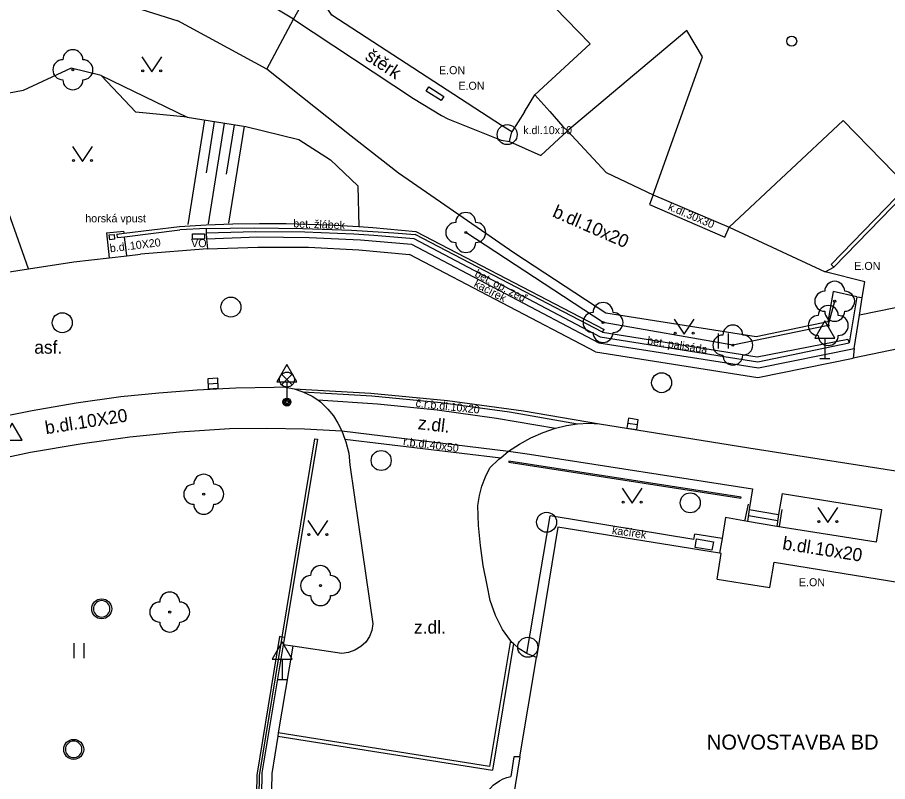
# Model space of a CAD drawing. Extents: x -598233 to -596890, y -1157848 to -1156431.
# Drawn here: x -598000.23 to -597956.73, y -1156818.81 to -1156780.59 of the extents above; entities that cross this region are included whole.
import ezdxf

# ---------------------------------------------------------------- set-up
doc = ezdxf.new("R2010")
doc.units = 0
for name, color, linetype in [('Level 10', 7, 'Continuous'), ('Level 11', 7, 'Continuous'), ('Level 14', 7, 'Continuous'), ('Level 15', 7, 'Continuous'), ('Level 22', 7, 'Continuous'), ('Level 23', 7, 'Continuous'), ('Level 24', 7, 'Continuous'), ('Level 27', 7, 'Continuous'), ('Level 28', 7, 'Continuous'), ('Level 33', 7, 'Continuous'), ('Level 34', 7, 'Continuous'), ('Level 36', 7, 'Continuous'), ('Level 40', 7, 'Continuous'), ('Level 41', 7, 'Continuous'), ('Level 42', 7, 'Continuous'), ('Level 5', 7, 'Continuous'), ('Level 6', 7, 'Continuous'), ('Level 7', 7, 'Continuous'), ('Level 8', 7, 'Continuous'), ('Level 9', 7, 'Continuous')]:
    doc.layers.add(name, color=color, linetype=linetype)

msp = doc.modelspace()

# ---------------------------------------------------------------- linework, layer by layer
at = {"layer": 'Level 10'}
for points in [[(-597990.73, -1156792.17), (-597988.21, -1156792.08), (-597985.68, -1156792.09), (-597983.16, -1156792.22), (-597980.64, -1156792.45)], [(-598000.74, -1156793.34), (-597999.67, -1156793.17), (-597997.42, -1156792.82), (-597995.65, -1156792.61), (-597994.77, -1156792.51), (-597994.08, -1156792.43)], [(-597990.73, -1156792.17), (-597994.08, -1156792.43)], [(-597971.34, -1156797.31), (-597980.64, -1156792.45)], [(-597953.48, -1156796.6), (-597958.46, -1156797.64)], [(-597971.34, -1156797.31), (-597963.22, -1156798.6)], [(-597963.22, -1156798.6), (-597958.46, -1156797.64)], [(-597995.07, -1156799.55), (-597993.16, -1156799.36), (-597991.24, -1156799.21), (-597989.32, -1156799.12), (-597987.4, -1156799.08)], [(-597987.4, -1156799.08), (-597986.91, -1156799.07), (-597986.4, -1156799.16), (-597985.97, -1156799.31)], [(-597985.97, -1156799.31), (-597985.5, -1156799.53), (-597985.22, -1156799.71), (-597985.08, -1156799.82), (-597984.71, -1156800.18)], [(-598003.87, -1156801.19), (-598001.69, -1156800.69), (-597999.49, -1156800.25), (-597997.29, -1156799.87), (-597995.07, -1156799.55)], [(-597984.71, -1156800.18), (-597984.44, -1156800.52), (-597984.21, -1156800.88), (-597984.02, -1156801.27)], [(-597975.14, -1156801.93), (-597974.56, -1156801.61), (-597973.96, -1156801.35), (-597973.33, -1156801.14)], [(-597973.33, -1156801.14), (-597972.79, -1156801), (-597972.23, -1156800.91), (-597971.69, -1156800.89), (-597971.14, -1156800.92)], [(-597971.14, -1156800.92), (-597963.67, -1156802.11)], [(-597984.02, -1156801.27), (-597983.86, -1156801.69), (-597983.81, -1156801.82)], [(-597983.81, -1156801.82), (-597983.67, -1156802.39), (-597983.61, -1156802.97)], [(-597976.61, -1156803.12), (-597976.16, -1156802.68), (-597976.07, -1156802.61), (-597975.68, -1156802.29), (-597975.14, -1156801.93)], [(-597963.67, -1156802.11), (-597953.34, -1156803.73)], [(-597983.61, -1156802.97), (-597983.19, -1156805.97)], [(-597977.21, -1156805), (-597977.14, -1156804.51), (-597977.02, -1156804.03), (-597976.84, -1156803.56), (-597976.61, -1156803.12)], [(-597977.09, -1156807), (-597977.18, -1156806), (-597977.21, -1156805)], [(-597983.19, -1156805.97), (-597982.46, -1156810.92)], [(-597976.75, -1156808.98), (-597976.95, -1156808), (-597977.09, -1156807)], [(-597976.6, -1156809.76), (-597976.75, -1156808.98)], [(-597976.34, -1156810.51), (-597976.6, -1156809.76)], [(-597975.51, -1156811.85), (-597975.58, -1156811.76), (-597975.98, -1156811.21), (-597976.34, -1156810.51)], [(-597982.46, -1156810.92), (-597982.51, -1156811.25), (-597982.63, -1156811.56), (-597982.82, -1156811.83), (-597983.07, -1156812.05)], [(-597984.02, -1156812.41), (-597986.47, -1156812.04), (-597986.94, -1156811.97)], [(-597983.07, -1156812.05), (-597983.36, -1156812.23), (-597983.68, -1156812.35), (-597984.02, -1156812.41)], [(-597974.29, -1156812.6), (-597974.74, -1156812.42), (-597974.77, -1156812.4), (-597975.15, -1156812.17), (-597975.44, -1156811.91), (-597975.51, -1156811.85)]]:
    msp.add_lwpolyline(points, dxfattribs=at)
at = {"layer": 'Level 11'}
for points in [[(-597974.37, -1156784.47), (-597971.6, -1156781.91), (-597978.08, -1156775.23), (-597959.82, -1156756.9), (-597957.84, -1156758.76), (-597959.27, -1156760.49)], [(-597986.43, -1156780.68), (-597993.45, -1156776.46)], [(-598002.82, -1156778.8), (-598002.27, -1156778.4), (-597998.93, -1156778.62), (-597992.22, -1156780.77)], [(-597986.43, -1156780.68), (-597985.5, -1156779.01)], [(-597987.77, -1156783.18), (-597992.22, -1156780.77)], [(-597987.77, -1156783.18), (-597986.43, -1156780.68)], [(-597986.43, -1156780.68), (-597980.44, -1156784.64)], [(-597968.45, -1156789.46), (-597965.98, -1156782.57), (-597966.77, -1156781.24), (-597972.73, -1156786.26)], [(-597983.55, -1156786.53), (-597987.77, -1156783.18)], [(-597980.44, -1156784.64), (-597979.03, -1156785.5)], [(-597979.03, -1156785.5), (-597978.72, -1156785.67)], [(-597978.72, -1156785.67), (-597976.05, -1156786.73)], [(-597955.75, -1156789.03), (-597958.96, -1156785.74), (-597964.65, -1156791.08)], [(-597975.63, -1156786.79), (-597975.51, -1156786.32)], [(-597974.06, -1156787.49), (-597972.73, -1156786.26)], [(-597981.18, -1156788.38), (-597983.55, -1156786.53)], [(-597976.05, -1156786.73), (-597975.63, -1156786.79)], [(-597975.63, -1156786.79), (-597974.06, -1156787.49)], [(-597975.42, -1156792.37), (-597981.18, -1156788.38)], [(-597968.45, -1156789.46), (-597968.64, -1156789.95)], [(-597968.64, -1156789.95), (-597964.87, -1156791.58)], [(-597995.27, -1156791.43), (-597994.9, -1156791.38), (-597992.13, -1156791.04)], [(-597992.13, -1156791.04), (-597990.8, -1156790.96)], [(-597990.8, -1156791.15), (-597992.11, -1156791.22)], [(-597990.8, -1156790.96), (-597989.46, -1156790.91), (-597988.13, -1156790.89), (-597986.79, -1156790.9)], [(-597986.79, -1156790.9), (-597984.63, -1156790.96), (-597983.17, -1156791.05), (-597982.47, -1156791.09), (-597980.32, -1156791.29)], [(-597964.87, -1156791.58), (-597964.65, -1156791.08)], [(-597995.78, -1156791.37), (-597994.91, -1156791.28)], [(-597995.78, -1156791.37), (-597995.65, -1156792.61)], [(-597995.27, -1156791.43), (-597995.25, -1156791.6)], [(-597995.25, -1156791.6), (-597994.88, -1156791.56), (-597992.11, -1156791.22)], [(-597994.9, -1156791.38), (-597994.91, -1156791.28)], [(-597994.77, -1156792.51), (-597994.88, -1156791.56)], [(-597990.8, -1156791.36), (-597988.33, -1156791.3), (-597985.87, -1156791.32), (-597983.41, -1156791.42)], [(-597990.78, -1156791.66), (-597988.22, -1156791.57), (-597985.65, -1156791.59), (-597983.09, -1156791.71), (-597980.53, -1156791.94)], [(-597983.41, -1156791.42), (-597982.41, -1156791.48), (-597981.42, -1156791.56), (-597980.42, -1156791.65)], [(-597980.42, -1156791.65), (-597971.1, -1156796.57)], [(-597980.32, -1156791.29), (-597970.91, -1156796.2)], [(-597990.78, -1156791.66), (-597990.73, -1156792.17)], [(-597980.53, -1156791.94), (-597971.17, -1156796.86)], [(-597970.82, -1156795.38), (-597975.42, -1156792.37)], [(-597957.87, -1156793.81), (-597959.85, -1156793.31)], [(-597958, -1156794.6), (-597957.87, -1156793.81)], [(-597959.45, -1156794.3), (-597959.73, -1156795.81)], [(-597958.27, -1156794.56), (-597959.45, -1156794.3)], [(-597958.41, -1156797.15), (-597958.14, -1156795.49), (-597958, -1156794.6)], [(-597953.56, -1156794.55), (-597958.14, -1156795.49)], [(-597963.31, -1156796.56), (-597970.82, -1156795.38)], [(-597959.73, -1156795.81), (-597963.31, -1156796.56)], [(-597970.98, -1156796.34), (-597970.91, -1156796.2)], [(-597971.17, -1156796.86), (-597963.18, -1156798.12)], [(-597971.1, -1156796.57), (-597963.22, -1156797.82)], [(-597963.22, -1156797.82), (-597958.65, -1156796.87)], [(-597963.18, -1156798.12), (-597958.41, -1156797.15)], [(-597958.41, -1156797.15), (-597958.46, -1156797.64)], [(-597986.4, -1156799.16), (-597982.56, -1156799.38), (-597978.74, -1156799.75), (-597974.93, -1156800.27), (-597971.14, -1156800.92)], [(-597985.97, -1156799.31), (-597982.51, -1156799.51), (-597979.07, -1156799.85), (-597975.64, -1156800.31), (-597972.23, -1156800.91)], [(-597985.22, -1156799.71), (-597982.23, -1156799.92), (-597979.25, -1156800.22), (-597976.28, -1156800.63), (-597973.33, -1156801.14)], [(-597999.57, -1156802.33), (-597997.1, -1156801.91), (-597994.62, -1156801.57), (-597992.13, -1156801.32), (-597989.63, -1156801.15)], [(-597989.63, -1156801.15), (-597987.76, -1156801.13), (-597985.89, -1156801.17), (-597984.02, -1156801.27)], [(-597984.02, -1156801.27), (-597975.68, -1156802.29)], [(-597985.39, -1156801.66), (-597985.24, -1156801.68), (-597986.88, -1156811.61)], [(-597983.86, -1156801.69), (-597976.07, -1156802.61)], [(-598002.86, -1156803.07), (-598001.22, -1156802.69), (-597999.57, -1156802.33)], [(-597975.68, -1156802.29), (-597974.64, -1156802.43)], [(-597974.64, -1156802.43), (-597963.48, -1156804.17)], [(-597975.66, -1156802.78), (-597975.66, -1156802.83), (-597964.07, -1156804.63), (-597964.06, -1156804.58)], [(-597963.48, -1156804.17), (-597963.65, -1156805.21)], [(-597962.01, -1156804.41), (-597962.18, -1156805.46)], [(-597962.01, -1156804.41), (-597957.04, -1156805.2)], [(-597974.77, -1156812.4), (-597973.61, -1156805.52)], [(-597966.42, -1156806.7), (-597973.61, -1156805.52)], [(-597963.65, -1156805.21), (-597963.74, -1156805.8)], [(-597963.69, -1156805.5), (-597962.22, -1156805.76)], [(-597963.65, -1156805.21), (-597962.18, -1156805.46)], [(-597962.18, -1156805.46), (-597962.27, -1156806.05)], [(-597957.04, -1156805.2), (-597957.31, -1156806.83)], [(-597964.84, -1156805.6), (-597965.01, -1156806.66), (-597965.13, -1156807.39)], [(-597963.74, -1156805.8), (-597964.84, -1156805.6)], [(-597962.27, -1156806.05), (-597963.74, -1156805.8)], [(-597966.42, -1156806.7), (-597966.37, -1156806.43)], [(-597965.01, -1156806.66), (-597966.37, -1156806.43)], [(-597957.31, -1156806.83), (-597962.27, -1156806.05)], [(-597995.6077, -1156810.17), (-597995.614, -1156810.0984), (-597995.6326, -1156810.029), (-597995.6629, -1156809.9638), (-597995.7042, -1156809.905), (-597995.755, -1156809.8542), (-597995.8138, -1156809.8129), (-597995.879, -1156809.7826), (-597995.9484, -1156809.764), (-597996.02, -1156809.7577), (-597996.0916, -1156809.764), (-597996.161, -1156809.7826), (-597996.2261, -1156809.8129), (-597996.285, -1156809.8542), (-597996.3358, -1156809.905), (-597996.3771, -1156809.9638), (-597996.4074, -1156810.029), (-597996.426, -1156810.0984), (-597996.4323, -1156810.17), (-597996.426, -1156810.2416), (-597996.4074, -1156810.311), (-597996.3771, -1156810.3761), (-597996.3358, -1156810.435), (-597996.285, -1156810.4858), (-597996.2261, -1156810.5271), (-597996.161, -1156810.5574), (-597996.0916, -1156810.576), (-597996.02, -1156810.5823), (-597995.9484, -1156810.576), (-597995.879, -1156810.5574), (-597995.8138, -1156810.5271), (-597995.755, -1156810.4858), (-597995.7042, -1156810.435), (-597995.6629, -1156810.3761), (-597995.6326, -1156810.311), (-597995.614, -1156810.2416), (-597995.6077, -1156810.17)], [(-597987.13, -1156811.56), (-597988.27, -1156818.49)], [(-597986.47, -1156812.04), (-597987.19, -1156816.38), (-597987.22, -1156816.54), (-597987.52, -1156818.41)], [(-597997.0077, -1156817.2), (-597997.014, -1156817.1284), (-597997.0326, -1156817.059), (-597997.0629, -1156816.9938), (-597997.1042, -1156816.935), (-597997.155, -1156816.8842), (-597997.2138, -1156816.8429), (-597997.279, -1156816.8126), (-597997.3484, -1156816.794), (-597997.42, -1156816.7877), (-597997.4916, -1156816.794), (-597997.561, -1156816.8126), (-597997.6261, -1156816.8429), (-597997.685, -1156816.8842), (-597997.7358, -1156816.935), (-597997.7771, -1156816.9938), (-597997.8074, -1156817.059), (-597997.826, -1156817.1284), (-597997.8323, -1156817.2), (-597997.826, -1156817.2716), (-597997.8074, -1156817.341), (-597997.7771, -1156817.4061), (-597997.7358, -1156817.465), (-597997.685, -1156817.5158), (-597997.6261, -1156817.5571), (-597997.561, -1156817.5874), (-597997.4916, -1156817.606), (-597997.42, -1156817.6123), (-597997.3484, -1156817.606), (-597997.279, -1156817.5874), (-597997.2138, -1156817.5571), (-597997.155, -1156817.5158), (-597997.1042, -1156817.465), (-597997.0629, -1156817.4061), (-597997.0326, -1156817.341), (-597997.014, -1156817.2716), (-597997.0077, -1156817.2)], [(-597975.41, -1156817.58), (-597975.56, -1156818.56)], [(-597975.11, -1156817.57), (-597975.41, -1156817.58)], [(-597988.27, -1156818.49), (-597988.44, -1156828.65), (-597988.52, -1156833.83)], [(-597987.52, -1156818.41), (-597987.79, -1156832.35)], [(-597976.13, -1156818.77), (-597975.95, -1156818.68), (-597975.76, -1156818.61), (-597975.56, -1156818.56)], [(-597976.95, -1156820.03), (-597976.88, -1156819.64), (-597976.71, -1156819.29), (-597976.45, -1156818.99), (-597976.13, -1156818.77)]]:
    msp.add_lwpolyline(points, dxfattribs=at)
at = {"layer": 'Level 14'}
msp.add_lwpolyline([(-597991.74, -1156785.58), (-597994.32, -1156785.33), (-597996.05, -1156783.5)], dxfattribs=at)
at = {"layer": 'Level 15'}
for points in [[(-597990.88, -1156785.72), (-597991.72, -1156790.94)], [(-597990.39, -1156785.8), (-597990.8, -1156788.36)], [(-597989.89, -1156785.88), (-597990.7, -1156790.91)], [(-597989.4, -1156785.96), (-597989.79, -1156788.43)], [(-597988.9, -1156786.03), (-597989.68, -1156790.88)]]:
    msp.add_lwpolyline(points, dxfattribs=at)
at = {"layer": 'Level 22'}
for centre in [(-597997.46, -1156783.21), (-597977.82, -1156791.35), (-597959.38, -1156794.79), (-597970.96, -1156795.85), (-597959.7, -1156796), (-597964.47, -1156796.98), (-597990.92, -1156804.44), (-597985.08, -1156809.01), (-597992.62, -1156810.33)]:
    msp.add_circle(centre, 0.05, dxfattribs=at)
for centre, start, end in [((-597997.46, -1156782.71), 0, 180), ((-597997.96, -1156783.21), 90, 270), ((-597996.96, -1156783.21), 270, 90), ((-597997.46, -1156783.71), 180, 0), ((-597977.82, -1156790.85), 0, 180), ((-597978.32, -1156791.35), 90, 270), ((-597977.32, -1156791.35), 270, 90), ((-597977.82, -1156791.85), 180, 0), ((-597959.38, -1156794.29), 0, 180), ((-597959.88, -1156794.79), 90, 270), ((-597958.88, -1156794.79), 270, 90), ((-597970.96, -1156795.35), 0, 180), ((-597959.7, -1156795.5), 0, 180), ((-597971.46, -1156795.85), 90, 270), ((-597970.46, -1156795.85), 270, 90), ((-597960.2, -1156796), 90, 270), ((-597959.38, -1156795.29), 180, 0), ((-597959.2, -1156796), 270, 90), ((-597964.47, -1156796.48), 0, 180), ((-597970.96, -1156796.35), 180, 0), ((-597964.97, -1156796.98), 90, 270), ((-597963.97, -1156796.98), 270, 90), ((-597959.7, -1156796.5), 180, 0), ((-597964.47, -1156797.48), 180, 0), ((-597990.92, -1156803.94), 0, 180), ((-597991.42, -1156804.44), 90, 270), ((-597990.42, -1156804.44), 270, 90), ((-597990.92, -1156804.94), 180, 0), ((-597985.08, -1156808.51), 0, 180), ((-597985.58, -1156809.01), 90, 270), ((-597984.58, -1156809.01), 270, 90), ((-597992.62, -1156809.83), 0, 180), ((-597993.12, -1156810.33), 90, 270), ((-597992.12, -1156810.33), 270, 90), ((-597985.08, -1156809.51), 180, 0), ((-597992.62, -1156810.83), 180, 0)]:
    msp.add_arc(centre, 0.5, start, end, dxfattribs=at)
at = {"layer": 'Level 23'}
for points in [[(-597996.05, -1156783.5), (-597997.54, -1156783.13), (-597999.95, -1156784.24), (-598002.66, -1156784.77)], [(-597996.05, -1156783.5), (-597991.74, -1156785.58)], [(-597999.67, -1156793.17), (-598002.66, -1156784.77)], [(-597991.74, -1156785.58), (-597988.81, -1156786.05), (-597986.17, -1156786.7), (-597984.58, -1156787.71)], [(-597984.58, -1156787.71), (-597983.21, -1156789.02), (-597983.17, -1156791.05)]]:
    msp.add_lwpolyline(points, dxfattribs=at)
at = {"layer": 'Level 24'}
for points in [[(-597979.8, -1156784.28), (-597979.67, -1156784.07), (-597978.92, -1156784.54), (-597979.05, -1156784.75)], [(-597979.05, -1156784.75), (-597979.8, -1156784.28)], [(-597995.64, -1156791.47), (-597995.4, -1156791.44)], [(-597995.62, -1156791.71), (-597995.64, -1156791.47)], [(-597995.4, -1156791.44), (-597995.38, -1156791.69)], [(-597991.48, -1156791.66), (-597991.48, -1156791.41)], [(-597991.48, -1156791.41), (-597990.88, -1156791.42)], [(-597990.88, -1156791.42), (-597990.88, -1156791.67)], [(-597995.38, -1156791.69), (-597995.62, -1156791.71)], [(-597991.48, -1156791.66), (-597990.88, -1156791.67)], [(-597965.52, -1156807.24), (-597966.36, -1156807.11), (-597966.28, -1156806.67), (-597965.44, -1156806.82)], [(-597965.44, -1156806.82), (-597965.52, -1156807.24)], [(-597975.58, -1156811.76), (-597976.63, -1156818.06)], [(-597975.44, -1156811.91), (-597976.49, -1156818.24)], [(-597976.63, -1156818.06), (-597987.19, -1156816.38)], [(-597987.22, -1156816.54), (-597976.49, -1156818.24)]]:
    msp.add_lwpolyline(points, dxfattribs=at)
at = {"layer": 'Level 27'}
for p, q in [((-597990.6998, -1156798.9106), (-597990.2002, -1156798.8894)), ((-597969.7272, -1156800.8827), (-597969.2328, -1156800.9573))]:
    msp.add_line(p, q, dxfattribs=at)
for points in [[(-597990.6892, -1156799.1604), (-597990.1896, -1156799.1392), (-597990.2108, -1156798.6396), (-597990.7104, -1156798.6608)], [(-597969.7645, -1156801.1299), (-597969.2701, -1156801.2045), (-597969.1955, -1156800.7101), (-597969.6899, -1156800.6355)]]:
    msp.add_lwpolyline(points, close=True, dxfattribs=at)
for centre in [(-597975.75, -1156786.45), (-597989.56, -1156795.08), (-597997.99, -1156795.86), (-597968.03, -1156798.86), (-597982.05, -1156802.75), (-597966.6, -1156804.87), (-597973.78, -1156805.84), (-597996.02, -1156810.17), (-597974.72, -1156812.09), (-597997.42, -1156817.2)]:
    msp.add_circle(centre, 0.5, dxfattribs=at)
at = {"layer": 'Level 28'}
msp.add_circle((-597961.53, -1156781.78), 0.25, dxfattribs=at)
at = {"layer": 'Level 33'}
for p, q in [((-597987.025, -1156798.97), (-597986.495, -1156798.44)), ((-597987.025, -1156798.44), (-597986.495, -1156798.97)), ((-597986.76, -1156799.08), (-597986.76, -1156799.83))]:
    msp.add_line(p, q, dxfattribs=at)
for centre, radius in [((-597986.76, -1156798.705), 0.375), ((-597986.76, -1156799.83), 0.2), ((-597986.76, -1156799.83), 0.1445), ((-597986.76, -1156799.83), 0.0876)]:
    msp.add_circle(centre, radius, dxfattribs=at)
at = {"layer": 'Level 34'}
for p, q in [((-597959.87, -1156796.632), (-597959.87, -1156797.65)), ((-597960.12, -1156797.65), (-597959.62, -1156797.65)), ((-597986.76, -1156798.812), (-597986.76, -1156799.83)), ((-597987, -1156812.682), (-597987, -1156813.7)), ((-597987.25, -1156813.7), (-597986.75, -1156813.7))]:
    msp.add_line(p, q, dxfattribs=at)
for points in [[(-597960.37, -1156796.632), (-597959.37, -1156796.632), (-597959.87, -1156795.766)], [(-597987.26, -1156798.812), (-597986.26, -1156798.812), (-597986.76, -1156797.946)], [(-598000.99, -1156801.742), (-597999.99, -1156801.742), (-598000.49, -1156800.876)], [(-597987.5, -1156812.682), (-597986.5, -1156812.682), (-597987, -1156811.816)]]:
    msp.add_lwpolyline(points, close=True, dxfattribs=at)
at = {"layer": 'Level 36'}
for p, q in [((-597965.184, -1156797.153), (-597965.184, -1156796.403)), ((-597964.684, -1156797.153), (-597964.684, -1156796.403)), ((-597997.394, -1156812.633), (-597997.394, -1156811.883)), ((-597996.894, -1156812.633), (-597996.894, -1156811.883))]:
    msp.add_line(p, q, dxfattribs=at)
for points in [[(-597994.02, -1156782.56), (-597993.52, -1156783.31), (-597993.02, -1156782.56)], [(-597997.48, -1156787.05), (-597996.98, -1156787.8), (-597996.48, -1156787.05)], [(-597967.4, -1156795.68), (-597966.9, -1156796.43), (-597966.4, -1156795.68)], [(-597970, -1156804.13), (-597969.5, -1156804.88), (-597969, -1156804.13)], [(-597960.22, -1156805.11), (-597959.72, -1156805.86), (-597959.22, -1156805.11)], [(-597985.72, -1156805.76), (-597985.22, -1156806.51), (-597984.72, -1156805.76)]]:
    msp.add_lwpolyline(points, dxfattribs=at)
for centre in [(-597993.9702, -1156783.2598), (-597993.0708, -1156783.2598), (-597997.4302, -1156787.7498), (-597996.5308, -1156787.7498), (-597967.3502, -1156796.3798), (-597966.4508, -1156796.3798), (-597969.9502, -1156804.8298), (-597969.0508, -1156804.8298), (-597960.1702, -1156805.8098), (-597959.2708, -1156805.8098), (-597985.6702, -1156806.4598), (-597984.7708, -1156806.4598)]:
    msp.add_circle(centre, 0.05, dxfattribs=at)
at = {"layer": 'Level 5'}
for points in [[(-597965.05, -1156807.4), (-597965.13, -1156807.39), (-597973.22, -1156806.08), (-597974.29, -1156812.6)], [(-597965.26, -1156808.69), (-597965.05, -1156807.4)], [(-597962.62, -1156809.11), (-597962.41, -1156807.83)], [(-597962.41, -1156807.83), (-597956.12, -1156808.85), (-597955.62, -1156808.93), (-597955.54, -1156808.94), (-597948.02, -1156810.16)], [(-597965.26, -1156808.69), (-597964, -1156808.89)], [(-597964, -1156808.89), (-597962.62, -1156809.11)], [(-597975.11, -1156817.57), (-597974.29, -1156812.6)], [(-597975.11, -1156817.57), (-597975.46, -1156819.73), (-597976.2, -1156824.21)]]:
    msp.add_lwpolyline(points, dxfattribs=at)
at = {"layer": 'Level 6'}
for points in [[(-597964, -1156808.89), (-597962.62, -1156809.11)], [(-597975.11, -1156817.57), (-597974.29, -1156812.6)]]:
    msp.add_lwpolyline(points, dxfattribs=at)
at = {"layer": 'Level 7'}
for points in [[(-597974.88, -1156785.32), (-597975.51, -1156786.32), (-597976.03, -1156786), (-597984.52, -1156780.48), (-597985.5, -1156779.01)], [(-597974.37, -1156784.47), (-597973.62, -1156785.3)], [(-597972.97, -1156786.04), (-597972.73, -1156786.26), (-597970.81, -1156788.35)], [(-597959.56, -1156792.95), (-597955.75, -1156789.03), (-597954.88, -1156788.13)], [(-597970.81, -1156788.35), (-597968.45, -1156789.46)], [(-597959.42, -1156793.09), (-597954.74, -1156788.27)], [(-597990.8, -1156791.15), (-597988.4, -1156791.11), (-597985.97, -1156791.14), (-597983.53, -1156791.23)], [(-597990.8, -1156791.15), (-597990.8, -1156791.36)], [(-597964.65, -1156791.08), (-597959.85, -1156793.31)], [(-597990.8, -1156791.36), (-597990.78, -1156791.66)], [(-597983.53, -1156791.23), (-597982.47, -1156791.29), (-597981.41, -1156791.36), (-597980.35, -1156791.45)], [(-597970.98, -1156796.34), (-597980.35, -1156791.45)], [(-597959.7, -1156796), (-597964.47, -1156796.98), (-597970.96, -1156795.85), (-597977.82, -1156791.35)], [(-597959.56, -1156792.95), (-597959.42, -1156793.09)], [(-597959.85, -1156793.31), (-597959.42, -1156793.09)], [(-597958.27, -1156794.56), (-597958.65, -1156796.87)], [(-597958.27, -1156794.56), (-597958, -1156794.6)], [(-597959.7, -1156796), (-597959.38, -1156794.79)], [(-597970.98, -1156796.34), (-597963.26, -1156797.57)], [(-597963.26, -1156797.57), (-597958.72, -1156796.68)], [(-597958.72, -1156796.68), (-597958.65, -1156796.87)], [(-597985.39, -1156801.66), (-597987.01, -1156811.59)], [(-597964.06, -1156804.58), (-597975.66, -1156802.78)], [(-597987.01, -1156811.59), (-597988.15, -1156818.5)], [(-597986.88, -1156811.61), (-597986.94, -1156811.97), (-597988.02, -1156818.37)], [(-597986.88, -1156811.61), (-597987.01, -1156811.59), (-597987.13, -1156811.56)], [(-597988.15, -1156818.5), (-597988.38, -1156833.7)], [(-597988.02, -1156818.37), (-597988.23, -1156832.97), (-597988.24, -1156833.61)]]:
    msp.add_lwpolyline(points, dxfattribs=at)
at = {"layer": 'Level 8'}
for points in [[(-597974.88, -1156785.32), (-597974.37, -1156784.47)], [(-597973.62, -1156785.3), (-597972.97, -1156786.04)], [(-597968.45, -1156789.46), (-597964.65, -1156791.08)]]:
    msp.add_lwpolyline(points, dxfattribs=at)
at = {"layer": 'Level 9'}
for points in [[(-597963.87, -1156805.79), (-597963.69, -1156804.94)], [(-597962.13, -1156806.06), (-597962, -1156805.2)]]:
    msp.add_lwpolyline(points, dxfattribs=at)

# ---------------------------------------------------------------- texts
at = {"layer": 'Level 40'}
for s, height, rotation, p in [('štěrk', 0.65, 326.5601, (-597982.9, -1156782.67)), ('k.dl.30x30', 0.4, 337, (-597967.74, -1156790.2)), ('b.dl.10x20', 0.65, 336.48015, (-597973.53, -1156790.54)), ('b.dl.10X20', 0.4, 7, (-597995.59, -1156792.34)), ('kačírek', 0.4, 332, (-597977.45, -1156794.03)), ('č.r.b.dl.10x20', 0.4, 354, (-597980.34, -1156800.07)), ('b.dl.10X20', 0.65, 8.96434, (-597998.8, -1156801.44)), ('z.dl.', 0.65, 353.22434, (-597980.24, -1156801.18)), ('r.b.dl.40x50', 0.4, 353, (-597980.97, -1156801.99)), ('kačírek', 0.4, 351.74615, (-597970.53, -1156806.42)), ('b.dl.10x20', 0.65, 351.03658, (-597962.02, -1156807.19))]:
    msp.add_text(s, height=height, rotation=rotation, dxfattribs=at).set_placement(p)
for s, height, p in [('k.dl.10x10', 0.4, (-597974.95, -1156786.43)), ('asf.', 0.65, (-597999.39, -1156797.41)), ('z.dl.', 0.65, (-597980.41, -1156811.41))]:
    msp.add_text(s, height=height, dxfattribs=at).set_placement(p)
at = {"layer": 'Level 41'}
for s, height, p in [('VO', 0.4, (-597991.55, -1156792.08)), ('NOVOSTAVBA BD', 0.75, (-597965.77, -1156817.21))]:
    msp.add_text(s, height=height, dxfattribs=at).set_placement(p)
at = {"layer": 'Level 42'}
for s, p in [('E.ON', (-597979.16, -1156783.43)), ('E.ON', (-597978.19, -1156784.21)), ('horská vpust', (-597996.84, -1156790.84)), ('E.ON', (-597958.4, -1156793.22)), ('E.ON', (-597961.17, -1156809.04))]:
    msp.add_text(s, height=0.4, dxfattribs=at).set_placement(p)
for s, rotation, p in [('bet. žlábek', 358, (-597986.45, -1156791.09)), ('bet. op. zeď', 332, (-597977.41, -1156793.52)), ('bet. palisáda', 351, (-597968.77, -1156796.93))]:
    msp.add_text(s, height=0.4, rotation=rotation, dxfattribs=at).set_placement(p)

doc.saveas('drawing.dxf')
